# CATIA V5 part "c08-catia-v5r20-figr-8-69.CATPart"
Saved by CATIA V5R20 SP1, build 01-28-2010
Part number: Part1
Bounding box of the stored display mesh (mm): x -75 to 75, y -65.851 to 65.851, z 0 to 50
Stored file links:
  D:\v5_r20\psrt_files_downloaded\c08-catia-v5r20-prt\c08-catia-v5r20-figr-8-69.CATPart
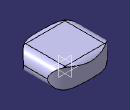
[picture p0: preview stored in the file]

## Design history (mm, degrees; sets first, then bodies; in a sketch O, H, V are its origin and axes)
Body1 (main body)
  Sketch1 on xy-plane, origin (0, 0, 0), H (1, 0, 0), V (0, 1, 0)
    line L1 (-75, 75) -> (75, 75)
    line L2 (75, 75) -> (75, -75)
    line L3 (75, -75) -> (-75, -75)
    line L4 (-75, -75) -> (-75, 75)
    axis line L5 (75, -75) -> (-75, 75)
    length L3 = 150
    length L2 = 150
    horizontal: L1 H, L3 H
    vertical: L2 V, L4 V
    midpoint: O L5
  Pad1: profile Sketch1, direction (0, 0, 1), length 50
  Fillet1: radius 25, on face of Pad1 (x6)
  Body2
    Sketch2 on xy-plane, origin (0, 0, 0), H (1, 0, 0), V (0, 1, 0)
      ellipse A1 centre (0, 0) semi-axes 84.7617, 65.8627 rotation 0
      point P1 (84.7617, 0)
      point P2 (0, 65.8627)
      coincidence: P1 H, P2 V, A1 P1, A1 P2
    Pad2: profile Sketch2, direction (0, 0, 1), length 50
  Intersect1: tool Body2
